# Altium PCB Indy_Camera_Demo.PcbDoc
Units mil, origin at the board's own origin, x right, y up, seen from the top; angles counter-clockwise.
Board outline 6000 x 3740.16 mil, 2 copper layers (Top Layer, Bottom Layer), stack 62.8 mil thick; 53 components, 50 nets, 311 pads, 54 vias.
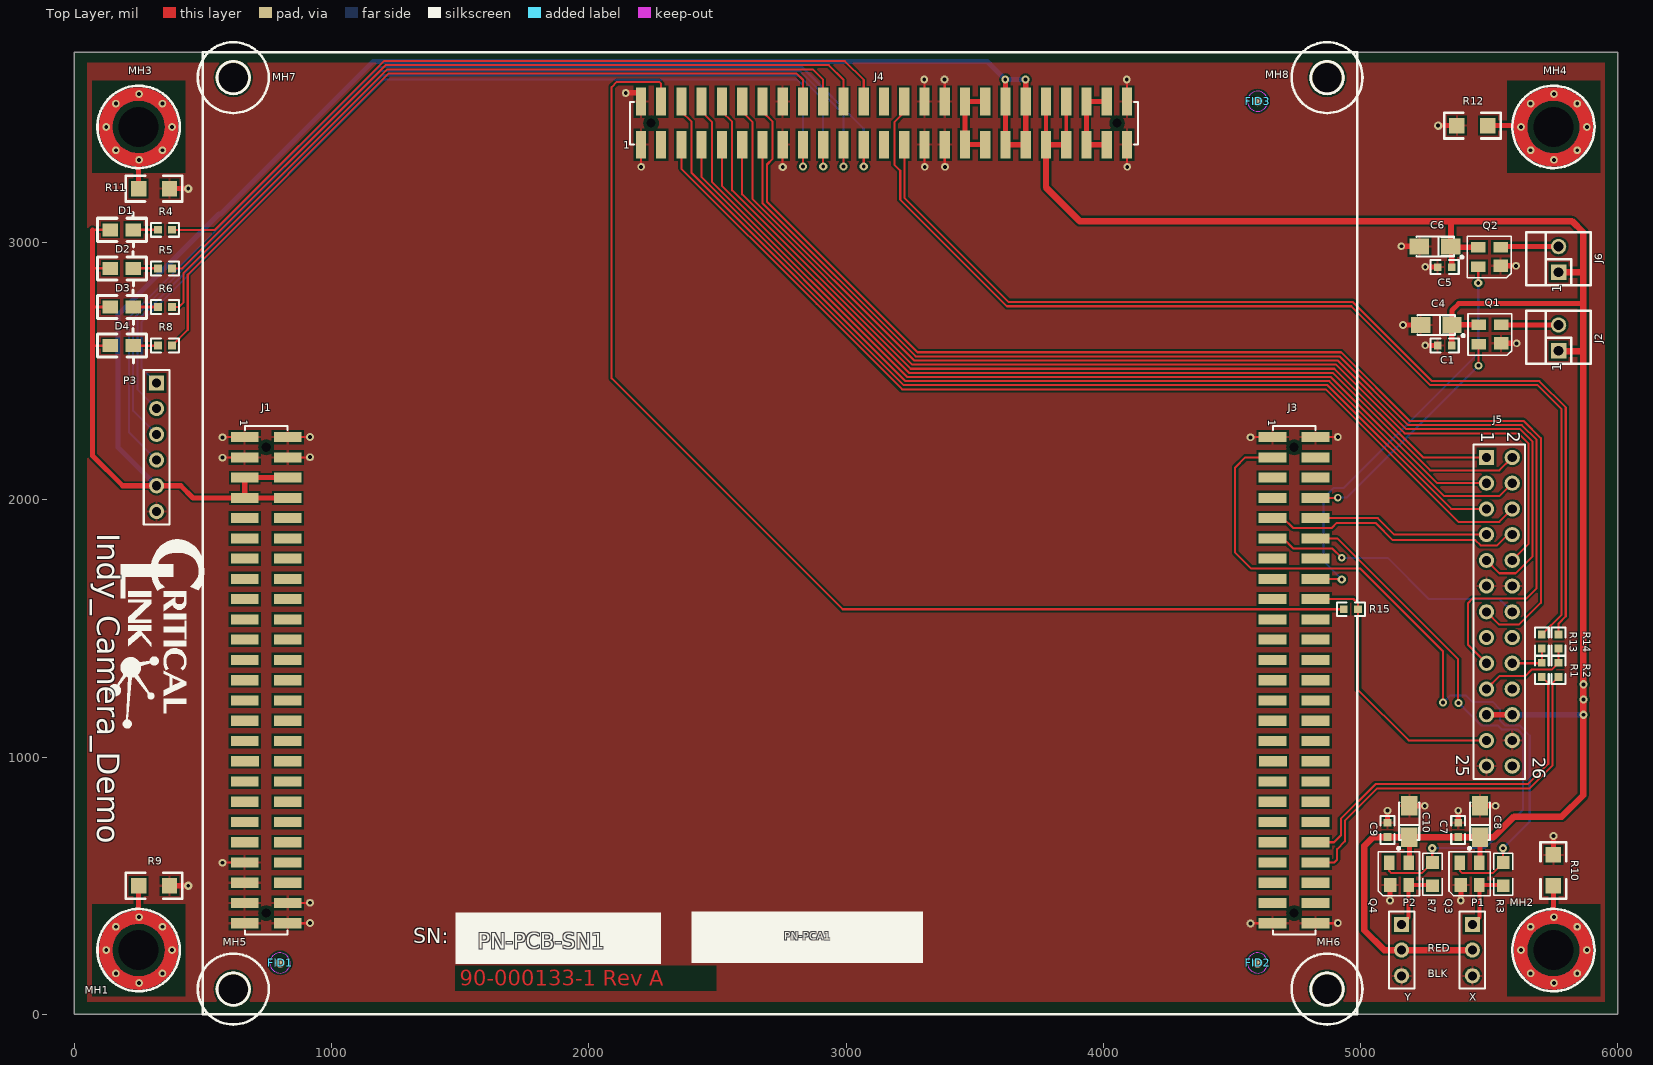
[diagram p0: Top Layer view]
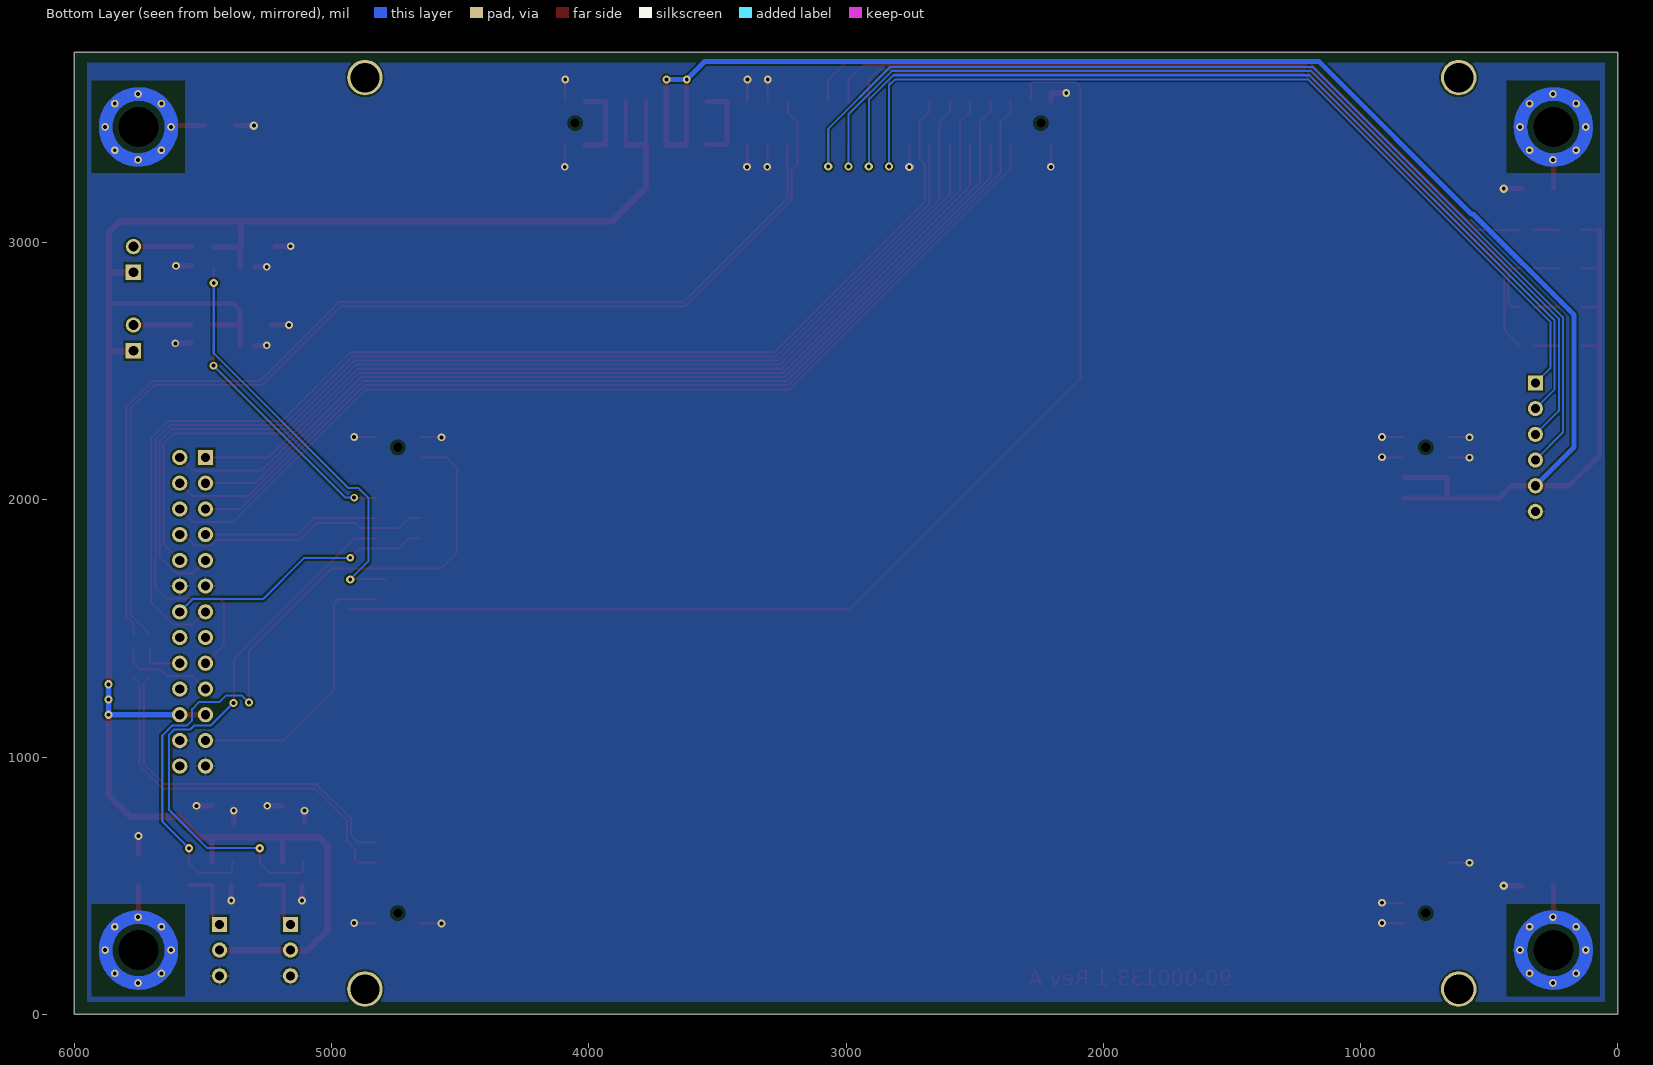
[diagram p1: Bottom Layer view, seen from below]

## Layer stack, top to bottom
Top Layer: signal copper 1.4
Dielectric: core 60, FR-4, Dk 4.8
Bottom Layer: signal copper 1.4

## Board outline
0,0 0,3740.16 6000,3740.16 6000,0

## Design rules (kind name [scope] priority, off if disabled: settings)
Clearance Clearance_pad2via [isvia vs ispad] p1: gap=16
Clearance [All] p2: gap=8
PolygonConnect PolygonConnect_via [isvia] p1: connectstyle=Direct reliefconductorwidth=10 reliefentries=4 polygonreliefangle="90 Angle"
PolygonConnect [All] p2: connectstyle=Relief reliefconductorwidth=10 reliefentries=4 polygonreliefangle="90 Angle"
RoomDefinition Indy_Camera_Demo [InComponentClass('Indy_Camera_Demo')] p1: confinementstyle=ConfineIn formatcopy=TRUE lockcomponents=FALSE outline 8500,0 9600,0 9600,2200 8500,2200
RoutingVias [All] p1: holewidth=15 width=30 viastyle="Through Hole" minholewidth=15 minwidth=28 maxholewidth=28 maxwidth=50
SilkscreenOverComponentPads [All] p1: minsilkscreentomaskgap=10
SolderMaskExpansion [All] p1: expansion=4
TestPointUsage [All] p1: valid=0 allowmultiple=FALSE
Testpoint [(IsPad And (OnTopLayer Or OnBottomLayer))] p1: side=3 testpointundercomponent=TRUE minsize=40 maxsize=100 preferedsize=60 minholesize=0 maxholesize=40 preferedholesize=32 testpointgrid=1 style=297 order=0-112345678
Width [All] p1: maxlimit=100 minlimit=8 preferedwidth=8
23 further rules are at their usual default settings.

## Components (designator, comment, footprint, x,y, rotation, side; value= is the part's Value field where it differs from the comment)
C1 "0.1uF" 0603 5355,2600 r180 top
C4 "4.7uF" SMD_TAN_A 5295,2680 r180 top
C5 "0.1uF" 0603 5355,2905 r180 top
C6 "4.7uF" SMD_TAN_A 5290,2985 r180 top
C7 "0.1uF" 0603 5380,690 r90 top
C8 "4.7uF" SMD_TAN_A 5465,750 r90 top
C9 "0.1uF" 0603 5105,690 r90 top
C10 "4.7uF" SMD_TAN_A 5190,750 r90 top
D1 "LED_0805_R" LED805 140,3050 r0 top
D2 "LED_0805_R" LED805 140,2900 r0 top
D3 "Green" LED805 140,2750 r0 top
D4 "Green" LED805 140,2600 r0 top
FID1 "FIDUCIAL" FIDUCIAL 800,200 r90 top
FID2 "FIDUCIAL" FIDUCIAL 4600,200 r90 top
FID3 "FIDUCIAL" FIDUCIAL 4600,3550 r90 top
J1 "87759-5050" 87759-5050 746.06,1299.21 r270 top locked
J2 "HDRLCK_0.1_1X2" 22-23-2021 5770,2580 r90 top
J3 "87759-5050" 87759-5050 4742.13,1299.21 r270 top locked
J4 "87759-5050" 87759-5050 3147.64,3464.57 r0 top locked
J5 "10-89-7261" HDR_M_100_2x13x240_THR_V_G 5540,1565 r270 top locked
J6 "HDRLCK_0.1_1X2" 22-23-2021 5770,2885 r90 top
MH1 "MH_5-32x" MH_5-32x#1 250,250 r0 top locked
MH2 "MH_5-32x" MH_5-32x#1 5750,250 r0 top locked
MH3 "MH_5-32x" MH_5-32x#1 250,3450 r0 top locked
MH4 "MH_5-32x" MH_5-32x#2 5750,3450 r0 top locked
MH5 "MH" MH125 618.11,98.43 r0 top locked
MH6 "MH" MH125 4870.08,98.43 r0 top locked
MH7 "MH" MH125 618.11,3641.73 r0 top locked
MH8 "MH" MH125 4870.08,3641.73 r0 top locked
P1 "22-28-4030" HDR_M_100_1x3x230_THR 5435,350 r270 top
P2 "22-28-4030" HDR_M_100_1x3x230_THR 5160,350 r270 top
P3 "22-28-4060" HDR1X6 320,2455 r270 top
PN-PCA1 "PN-PCA" PN-PCA 3300,400 r180 top
PN-PCB-SN1 "90-000133-1 Rev A" PN-PCB 1485,460 r0 top
Q1 "MIC4416YM4" SM/SOT143_1234 5547.04,2608.77 r90 top
Q2 "MIC4416YM4" SM/SOT143_1234 5545,2910 r90 top
Q3 "MIC4416YM4" SM/SOT143_1234 5390,503 r0 top
Q4 "MIC4416YM4" SM/SOT143_1234 5115.23,503.04 r0 top
R1 "0.0" 0603 5705,1367 r270 top
R2 "0.0" 0603 5770,1367 r270 top
R3 "0.0" 0805 5555,590 r270 top
R4 "1.00K" 0603 380,3050 r180 top
R5 "1.00K" 0603 380,2900 r180 top
R6 "1.00K" 0603 380,2750 r180 top
R7 "0.0" 0805 5280,590 r270 top
R8 "1.00K" 0603 380,2600 r180 top
R9 "0.0" 1206 250,500 r0 top
R10 "0.0" 1206 5750,500 r90 top
R11 "0.0" 1206 250,3210 r0 top
R12 "0.0" 1206 5495,3455 r180 top
R13 "0.0" 0603 5705,1422 r90 top
R14 "0.0" 0603 5770,1477 r270 top
R15 "0.0" 0603 4935,1575 r0 top

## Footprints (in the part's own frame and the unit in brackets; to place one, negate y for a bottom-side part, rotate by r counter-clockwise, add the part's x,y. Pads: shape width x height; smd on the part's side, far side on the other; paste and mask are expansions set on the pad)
22-23-2021 [mil] "Molex Header, Straight-Friction-Lock, 1x2"
  rect 60x60 hole 38: 1(0,0)
  round 60 hole 38: 2(100,0)
  silkscreen extent -50,-125 155,125
0603 [mil]
  rect 30x30 smd: 1(0,0) 2(55,0)
  silkscreen extent -27,-27 82,27
0805 [mil]
  rect 50x50 smd: 1(0,0) 2(90,0)
  silkscreen extent -37,-37 127,37
1206 [mil]
  rect 60x60 smd: 1(0,0) 2(120,0)
  silkscreen extent -50,-50 170,50
87759-5050 [mm] "Male Receptacle, 2x25, 2mm Pitch"
  round 0 hole 0.9 unplated: 0(-23,0) 0(23,0)
  rect 1x2.75 smd: 1(-24,-2.125) 2(-24,2.125) 3(-22,-2.125) 4(-22,2.125) 5(-20,-2.125) 6(-20,2.125) 7(-18,-2.125) 8(-18,2.125) 9(-16,-2.125) 10(-16,2.125) 11(-14,-2.125) 12(-14,2.125) 13(-12,-2.125) 14(-12,2.125) 15(-10,-2.125) 16(-10,2.125) 17(-8,-2.125) 18(-8,2.125) 19(-6,-2.125) 20(-6,2.125) 21(-4,-2.125) 22(-4,2.125) 23(-2,-2.125) 24(-2,2.125) 25(0,-2.125) 26(0,2.125) 27(2,-2.125) 28(2,2.125) 29(4,-2.125) 30(4,2.125) 31(6,-2.125) 32(6,2.125) 33(8.003,-2.1) 34(8,2.125) 35(10,-2.125) 36(10,2.125) 37(12,-2.125) 38(12,2.125) 39(14,-2.125) 40(14,2.125) 41(16,-2.125) 42(16,2.125) 43(18,-2.125) 44(18,2.125) 45(20,-2.125) 46(20,2.125) 47(22,-2.125) 48(22,2.125) 49(24,-2.125) 50(24,2.125)
  Top Layer pour cut-out: -23.762,0 -23.704,-0.292 -23.539,-0.539 -23.292,-0.704 -23,-0.762 -23,-0.762 -22.709,-0.704 -22.461,-0.539 -22.296,-0.292 -22.238,0 -22.238,0 -22.296,0.292 -22.461,0.539 -22.709,0.704 -23,0.762 -23,0.762 -23.292,0.704 -23.539,0.539 -23.704,0.292 -23.762,0
  Top Layer pour cut-out: 22.238,0 22.296,-0.292 22.461,-0.539 22.708,-0.704 23,-0.762 23,-0.762 23.291,-0.704 23.539,-0.539 23.704,-0.292 23.762,0 23.762,0 23.704,0.292 23.539,0.539 23.291,0.704 23,0.762 23,0.762 22.708,0.704 22.461,0.539 22.296,0.292 22.238,0
  Bottom Layer pour cut-out: 22.238,0 22.296,-0.292 22.461,-0.539 22.708,-0.704 23,-0.762 23,-0.762 23.291,-0.704 23.539,-0.539 23.704,-0.292 23.762,0 23.762,0 23.704,0.292 23.539,0.539 23.291,0.704 23,0.762 23,0.762 22.708,0.704 22.461,0.539 22.296,0.292 22.238,0
  Bottom Layer pour cut-out: -23.762,0 -23.704,-0.292 -23.539,-0.539 -23.292,-0.704 -23,-0.762 -23,-0.762 -22.709,-0.704 -22.461,-0.539 -22.296,-0.292 -22.238,0 -22.238,0 -22.296,0.292 -22.461,0.539 -22.709,0.704 -23,0.762 -23,0.762 -23.292,0.704 -23.539,0.539 -23.704,0.292 -23.762,0
  silkscreen extent -25.1,-2.1 25.1,2.1, body extent -24.96,-2.75 24.94,2.75, height 6.48
FIDUCIAL [mm] "Fiducial mark"
  round 1 smd paste-0.5 mask+0.5: FID(0,0)
  Top Layer keep-out circle w0.025: c0,0 r1
HDR1X6 [mm] "Connector; Header; 6 Position"
  rect 1.5x1.5 hole 0.9: 1(0,0)
  round 1.5 hole 0.9: 2(2.54,0) 3(5.08,0) 4(7.62,0) 5(10.16,0) 6(12.7,0)
  silkscreen extent -1.27,-1.27 13.97,1.27
HDR_M_100_1x3x230_THR [mm] "Connector; Header; 3 Position"
  rect 1.5x1.5 hole 0.9: 1(0,0)
  round 1.5 hole 0.9: 2(2.54,0) 3(5.08,0)
  silkscreen extent -1.27,-1.27 6.35,1.27
HDR_M_100_2x13x240_THR_V_G [mm] "Connector; Header; 13x2 Position"
  rect 1.5x1.5 hole 0.9: 1(-15.24,-1.27)
  round 1.5 hole 0.9: 2(-15.24,1.27) 3(-12.7,-1.27) 4(-12.7,1.27) 5(-10.16,-1.27) 6(-10.16,1.27) 7(-7.62,-1.27) 8(-7.62,1.27) 9(-5.08,-1.27) 10(-5.08,1.27) 11(-2.54,-1.27) 12(-2.54,1.27) 13(0,-1.27) 14(0,1.27) 15(2.54,-1.27) 16(2.54,1.27) 17(5.08,-1.27) 18(5.08,1.27) 19(7.62,-1.27) 20(7.62,1.27) 21(10.16,-1.27) 22(10.16,1.27) 23(12.7,-1.27) 24(12.7,1.27) 25(15.24,-1.27) 26(15.24,1.27)
  silkscreen extent -16.51,-2.54 16.51,2.54
LED805 [mil]
  rect 60x50 smd: 1(0,0) 2(90,0)
  silkscreen extent -50,-67 140,66
MH125 [mm] "Mounting Holes Dia 0.125,Pad 0.250"
  round 3.5 hole 2.9: 0(0,0)
  silkscreen extent -3.5,-3.5 3.5,3.5
MH_5-32x#1 [mil] "MH for screw"
  round 30 hole 15: 0(-126,0) 0(-88.51,-90.51) 0(-88.51,90.51) 0(2,-128) 0(2,128) 0(92.51,-90.51) 0(92.51,90.51) 0(130,0)
  round 0 hole 156.3 unplated mask+0: 1(0,0)
  Top Layer circle w52.5: c0,0 r128
  Bottom Layer circle w52.5: c0,0 r128
  silkscreen extent -160,-160 160,160
MH_5-32x#2 [mil] "MH for screw"
  round 30 hole 15: 0(-126,0) 0(-88.51,-90.51) 0(-88.51,90.51) 0(2,-128) 0(2,128) 0(92.51,-90.51) 0(92.51,90.51) 0(130,0)
  round 0 hole 156.3 unplated mask+0: 1(0,0)
  Top Layer circle w52.5: c0,0 r128
  Top Layer lines w52.5: -128,0 cw(c0,0) -127.98,1.98 cw(c0,0) 128,0
  Bottom Layer circle w52.5: c0,0 r128
  silkscreen extent -160,-160 160,160
PN-PCA [mil] "PN-PCA silkscreen"
  silkscreen extent 0,0 900,200
PN-PCB [mil] "PN-PCB cooper"
  silkscreen extent -4,-264 796,-64
SM/SOT143_1234 [mil]
  rect 48x56 smd: 1(0.23,0.04)
  rect 40x56 smd: 2(72.23,0.04) 3(72.23,87.04) 4(-3.77,87.04)
  silkscreen extent -46,-41 114,129
SMD_TAN_A [mm]
  rect 1.9x1.6 smd: 1(-1.55,0) 2(1.55,0)
  silkscreen extent -2.78,-1 1.85,1.17

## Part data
C1 C5 C7 C9: library part CAP_X7R_0603_50V, "CAP CER .10UF 50V X7R 10% 0603"
C4 C6 C8 C10: library part T491A475K016AT, "CAPACITOR TANT 4.7UF 16V 10% SMD"
D1 D2: "LED SUPER RED CLEAR 0805 SMD"
D3 D4: library part LED805_G, "LED THIN 565NM GRN DIFF 0805 SMD"
FID1 FID2 FID3: "Fiducial mark"
J1 J3 J4: library part HDR_M_2mm_2x25x150_SMD_V_G, "CONN HEADER 50POS 2MM VERT SMD"
J2 J6: library part 22-23-2021, "CONN HEADER 2POS .100 VERT TIN"
J5: library part HDR_M_100_2x13x240_THR_V_G, "CONN HDR DUAL 26POS .100 SRT TIN"
P1 P2: library part HDR_M_100_1x3x230_THR_V, "CONN HEADER 3POS .100 VERT TIN"
P3: library part HDR_M_100_1x6x230_THR_V, "CONN HEADER 6POS .100 VERT TIN"
PN-PCA1: "PCA Part number"
PN-PCB-SN1: library part PN-PCB-SN, "PCB Serial Number and Part Number"
Q1 Q2 Q3 Q4: "IC DRIVER MOSF LOW SIDE SOT143-4"
R1 R2 R13 R14 R15: library part ZERO_0603, "RES 0.0 OHM 1/10W 5% 0603 SMD"
R3 R7: library part ZERO_0805, "RES 0.0 OHM 1/8W 5% 0805 SMD"
R4 R5 R6 R8: library part RES_0603, "RES 1.00K OHM 1/10W 1% 0603 SMD"
R9 R10 R11 R12: library part RES_1206, "RES  0.0 OHM 1/4W 5% 1206 SMD"

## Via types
v1: diameter 30, hole 15, Top Layer to Bottom Layer, 36 vias
v2: diameter 32, hole 15, Top Layer to Bottom Layer, 18 vias

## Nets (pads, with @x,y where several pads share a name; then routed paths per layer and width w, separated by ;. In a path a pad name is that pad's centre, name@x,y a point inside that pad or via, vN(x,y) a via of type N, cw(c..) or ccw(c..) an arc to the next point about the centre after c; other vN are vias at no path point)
+3.3V: D1.1 D2.1 D3.1 D4.1 J1.5 J1.6 J1.7 J1.8 J4.37 J4.38 J4.39 J4.40 P3.5 | length 7498.9
  Top Layer w10: 72,2600 D4.1 ; 72,2750 D3.1 ; 72,3050 D1.1 ; 73,2900 D2.1
  Top Layer w20: 71,3049 71,2172 188,2055 P3.5 414,2055 461.13,2007.87 J1.7 ; J1.8 J1.7 ; J1.6 J1.5 J1.7 ; v1@3620.08,3634.44 J4.38 J4.37 J4.39 v1@3698.82,3634.44
  Bottom Layer w20: P3.5 170,2205 170,2720 562,3112 569,3112 1162,3705 3548.61,3705 v1(3619.17,3634.44) v1(3697.91,3634.44)
+5V: C1.1 C4.1 C5.1 C6.1 C7.1 C8.1 C9.1 C10.1 J2.1 J4.41 J4.42 J4.43 J4.44 J5.21 J5.22 J6.1 P1.2 P2.2 Q1.3 Q2.3 Q3.3 Q4.3 | length 8581.2
  Top Layer w15: J4.41 J4.42 ; J4.43 J4.44
  Top Layer w20: J4.41 J4.43 ; P2.2 P2.2@5161,249 ; Q4.3@5187.23,590.04 5190,592.81 C10.1 C10.1@5188.98,690 ; C6.1 C6.1@5353.8,2982.23 ; C1.1 5355,2678.98 C4.1 ; C5.1 5355,2981.02 C6.1@5353.8,2982.23 ; Q2.3 C6.1@5353.8,2982.23 ; Q1.3 5357.02,2681 C4.1 ; Q3.3 5465,592.81 C8.1 ; J5.21 J5.22 ; 5866,2763 5382,2763 5356.02,2737.02 C4.1
  Top Layer w25: J4.41 3777.56,3214.44 3908,3084 5352,3084 ; P2.2 5092,250 5015,327 5015,655 5048.98,688.98 5103.98,688.98 C9.1 5106.02,688.98 C10.1 C8.1 5516.98,688.98 5597,769 5642,769 5783,769 5866,852 5866,2578 ; P2.2@5161,250 P1.2 ; C6.1 5352,2985.98 5352,3084 ; J2.1 5772,2578 5866,2578 ; J6.1 5862,2885 5866,2889 ; 5352,3084 5822,3084 5866,3040 5866,2889 ; 5866,2578 5866,2763 5866,2889
  Bottom Layer w20: J5.22 v2(5867,1165) v2(5867,1224) v2(5867,1283)
+12VF: J4.45 J4.46 J4.47 J4.48 | length 324.8
  Top Layer w20: J4.47 J4.45 J4.46 J4.48
-12V: J4.33 J4.34 J4.35 J4.36 | length 324.2
  Top Layer w20: J4.35 3540.35,3381.89 J4.33 3462.72,3548.11 J4.34 J4.36
D0: J4.12 J5.9 | length 4490.7
  Top Layer w8: J4.12 2596.46,3509.76 2636.22,3470 2636.22,3170.41 3264.63,2542 4911.75,2542 5178.75,2275 5620.75,2275 5669,2226.75 5669,1781 5603,1715 5540,1715 J5.9
D1: J4.11 J5.10 | length 4131.8
  Top Layer w8: J4.11 2596.46,3187.54 3258,2526 4905.12,2526 5172.12,2259 5614.12,2259 5653,2220.12 5653,1828 J5.10
D1_ON_OFF: J3.8 Q1.4 | length 929.2
  Top Layer w8: J3.8 v1@4912,2007.87 ; v1(5459,2522) 5459,2604 Q1.4
  Bottom Layer w8: v1(4912,2008.78) 4945.78,2008.78 v1(5459,2522)
D2: J4.10 J5.1 | length 3723.6
  Top Layer w8: J4.10 2517.72,3509.76 2557.48,3470 2557.48,3203.89 3251.37,2510 4898.49,2510 5243.49,2165 J5.1
D2_ON_OFF: J3.16 Q2.4 | length 1655.9
  Top Layer w8: J3.16@4787.91,1692.91 J3.16 4925.09,1692.91 v2(4927,1691) ; v2(5457.96,2843) Q2.4
  Bottom Layer w8: v2(4927,1691) 4857,1761 4857,2008 4895,2046 4934,2046 5457.96,2569.96 v2(5457.96,2843)
D3: J4.9 J5.2 | length 3711
  Top Layer w8: J4.9 2517.72,3221.03 3244.75,2494 4891.86,2494 5270.86,2115 5540,2115 J5.2
D4: J4.8 J5.3 | length 3824.2
  Top Layer w8: J4.8 2438.98,3509.76 2478.74,3470 2478.74,3237.38 3238.12,2478 4885.24,2478 5298.24,2065 J5.3
D5: J4.7 J5.4 | length 3811.5
  Top Layer w8: J4.7 2438.98,3254.51 3231.49,2462 4878.61,2462 5325.61,2015 5540,2015 J5.4
D6: J4.6 J5.5 | length 3924.7
  Top Layer w8: J4.6 2360.24,3509.76 2400,3470 2400,3270.86 3224.86,2446 4871.98,2446 5352.98,1965 J5.5
D7: J4.5 J5.6 | length 3921.9
  Top Layer w8: J4.5 2360.24,3288 2885.69,2762.55 3218.24,2430 4865.35,2430 5310.39,1984.96 ; 5317.35,1978 5310.39,1984.96 ; J5.6 5540,1915 5380.35,1915 5310.39,1984.96
D8: J3.10 J5.7 | length 690.8
  Top Layer w8: J3.10 5067.87,1929.13 5132,1865 J5.7
D9: J3.9 J5.8 | length 1009.1
  Top Layer w8: J3.9 4699.87,1929.13 4738,1891 4888,1891 4908,1911 5058.3,1911 5125.3,1844 5446.47,1844 5467,1823.47 5531.53,1823.47 5573.06,1865 J5.8
EXPOSURE: J3.11 J5.14 | length 1049.7
  Top Layer w8: J3.11 4699.61,1850.39 4739,1811 4891,1811 v1(4927,1775)
  Bottom Layer w8: v1(4927,1775) 5106,1775 5266,1615 5540,1615 J5.14
FV: J4.13 J5.17 | length 4785.2
  Top Layer w8: J4.13 2675.2,3154.06 3271.26,2558 4918.37,2558 5185.37,2291 5627.37,2291 5685,2233.37 5685,1744 ; J5.17 5418,1437 5418,1599 5435,1616 5644,1616 5685,1657 5685,1744 ; 5685,1708 5685,1744
GND: C1.2 C4.2 C5.2 C6.2 C7.2 C8.2 C9.2 C10.2 J1.1 J1.2 J1.3 J1.4 J1.43 J1.45 J1.47 J1.48 J1.49 J1.50 J3.1 J3.2 J3.49 J3.50 J4.1 J4.2 J4.15 J4.16 J4.29 J4.30 J4.31 J4.32 J4.49 J4.50 J5.11 J5.12 J5.24 J5.25 P1.3 P2.3 P3.6 Q1.1 Q2.1 Q3.1 Q4.1 R9.2 R10.2 R11.2 R12.2 | length 2689.1
  Top Layer w8: v1@576.19,590.55 J1.43 ; v1@576.19,2165.35 J1.3 ; v1@576.19,2244.09 J1.1 ; J1.50 v1@915.94,354.33 ; J1.48 v1@915.94,433.07 ; J1.4 v1@915.94,2165.35 ; J1.2 v1@915.94,2244.09 ; v1@2202.76,3294.69 J4.1 ; v2(2753.94,3294.69) J4.15 ; v1@3305.12,3294.69 J4.29 ; J4.30 v1@3305.12,3634.44 ; v1@3383.86,3294.69 J4.31 ; J4.32 v1@3383.86,3634.44 ; v1@4092.52,3294.69 J4.49 ; J4.50 v1@4092.52,3634.44 ; v1@4572.25,354.33 J3.49 ; v1@4572.25,2244.09 J3.1 ; J3.50 v1@4912,354.33 ; J3.2 v1@4912,2244.09
  Top Layer w20: R9.2 v2(443,500) ; R11.2 v2(443,3210) ; v1@2146.76,3582.76 2202.76,3582.76 J4.2 ; C9.2 v1(5105,792) ; v1(5115,443) 5115.23,443.23 Q4.1@5115.23,503.04 ; v1@5159.19,2986 C6.2@5219,2986 ; v1@5174.17,2680 C4.2 ; C10.2 v1@5249.81,811.02 ; v1(5252,2601) C1.2@5299,2601 ; v1(5252,2906) 5299,2906 C5.2 ; v2(5302,3455) R12.2 ; C7.2 v1(5380,792) ; v1(5390,443) 5390.23,443.23 Q3.1 ; C8.2 v1@5524.81,811.02 ; Q2.1 v1@5604.77,2910.23 ; Q1.1 v1@5606.81,2609 ; R10.2 v2(5750,693)
  other v1: 4572.25,353.43 915.94,355.24 4912,355.24 915.94,433.98 576.19,589.65 5250.04,810.8 5525.04,810.8 576.19,2164.45 915.94,2166.26 576.19,2243.19 4572.25,2243.19 915.94,2245 4912,2245 5607.04,2608.77 5165,2680 5605,2910 5158.96,2986.23 2203.66,3294.69 3306.02,3294.69 3384.76,3294.69 4093.43,3294.69 2144,3582 3304.21,3634.44 3382.95,3634.44 4091.61,3634.44
I2C0_SCL: J5.19 R2.1 R14.2 | length 377.2
  Top Layer w8: J5.19 5540,1315 5640,1315 5665,1340 5743,1340 R2.1 R14.2
I2C0_SDA: J5.18 R1.1 R13.1 | length 213.7
  Top Layer w8: J5.18@5592,1367 J5.18 ; 5630,1365 J5.18 ; R13.1 R1.1 5703,1365 J5.18
LED_1: J4.24 R4.1 | length 3075.4
  Top Layer w8: R4.1 547.12,3050 1203.12,3706 2995.57,3706 3068.9,3632.68 J4.24
LED_2: J4.22 R5.1 | length 3048.4
  Top Layer w8: R5.1 419.75,2900 1209.75,3690 2932.83,3690 2990.16,3632.68 J4.22
  Top Layer w10: R5.1 R5.1@382,2902
LED_3: J4.20 R6.1 | length 3082.3
  Top Layer w8: R6.1 406,2750 425.07,2769.07 425.07,2882.69 1216.37,3674 2870.09,3674 2911.42,3632.68 J4.20
LED_4: J4.18 R8.1 | length 3111.8
  Top Layer w8: R8.1 441.07,2661.07 441.07,2876.07 1223,3658 2807.35,3658 2832.68,3632.68 J4.18
LV: J4.14 J5.13 | length 4710.4
  Top Layer w8: J4.14 2675.2,3509.76 2714.96,3470 2714.96,3326 2693,3304.04 2693,3158.88 3277.88,2574 4925,2574 5192,2307 5634,2307 5701,2240 5701,1600 5616,1515 5540,1515 J5.13
NetD1_2: D1.2 R4.2 | length 95
  Top Layer w10: D1.2 R4.2
NetD2_2: D2.2 R5.2 | length 95
  Top Layer w10: D2.2 R5.2
NetD3_2: D3.2 R6.2 | length 95
  Top Layer w10: D3.2 R6.2
NetD4_2: D4.2 R8.2 | length 95
  Top Layer w10: D4.2 R8.2
NetJ2_2: J2.2 Q1.2 | length 223.4
  Top Layer w20: Q1.2 5548,2680 J2.2
NetJ4_17: J4.17 P3.1 | length 3632.3
  Top Layer w8: v2(2832.68,3296.46) J4.17
  Bottom Layer w8: P3.1 261,2514 261,2691 1205,3635 2809,3635 2832.68,3611.32 v2(2832.68,3296.46)
NetJ4_19: J4.19 P3.2 | length 3817.9
  Top Layer w8: v2(2911.42,3296.46) J4.19
  Bottom Layer w8: P3.2 245,2430 245,2697.63 1198.37,3651 2815.63,3651 2911.42,3555.21 v2(2911.42,3296.46)
NetJ4_21: J4.21 P3.3 | length 4003.5
  Top Layer w8: v2(2990.16,3296.46) J4.21
  Bottom Layer w8: P3.3 229,2346 229,2704.25 1191.75,3667 2822.25,3667 2990.16,3499.1 v2(2990.16,3296.46)
NetJ4_23: J4.23 P3.4 | length 4209.2
  Top Layer w8: v2(3068.9,3296.46) J4.23
  Top Layer w10: P3.4 P3.4@340,2155
  Bottom Layer w8: P3.4 213,2262 213,2710.88 1185.12,3683 2828.88,3683 3068.9,3442.98 v2(3068.9,3296.46)
NetJ4_27: J4.27 R14.1 | length 4029.1
  Top Layer w8: J4.27 3227,3380.28 3227,3174 3632,2769 4971,2769 5278,2462 5695.63,2462 5798,2359.63 5798,1547.37 5770,1519.37 ; R14.1 5770,1519.37 ; 5770,1500 5770,1519.37
NetJ4_28: J4.28 R13.2 | length 4222.5
  Top Layer w8: J4.28 3226.38,3506.38 3188,3468 3188,3303 3211,3280 3211,3167.37 3625.37,2753 4964.37,2753 5271.37,2446 5689,2446 5782,2353 5782,1554 R13.2
NetJ6_2: J6.2 Q2.2 | length 226.2
  Top Layer w20: Q2.2 5547.73,2985 J6.2
NetMH1_0: MH1.0 R9.1 | length 122.8
  Top Layer w20: R9.1 250,380 MH1.0@252,378
NetMH2_0: MH2.0 R10.1 | length 122.8
  Top Layer w20: R10.1 5750,380 MH2.0@5752,378
NetMH3_0: MH3.0 R11.1 | length 112.8
  Top Layer w20: R11.1 250,3320 MH3.0@252,3322
NetMH4_0: MH4.0 R12.1 | length 131.1
  Top Layer w20: R12.1 5619,3455 5622.02,3451.98 MH4.0@5624,3450
PIXCLK: J3.18 J5.23 R15.2 | length 1089.2
  Top Layer w8: J3.18 4826.61,1615 4973,1615 4990,1598 R15.2 4990,1262 5187,1065 5367,1065 J5.23
PIXCLK_1: J4.4 R15.1 | length 4623.1
  Top Layer w8: J4.4 2281.5,3617.5 2274,3625 2109,3625 2089,3605 2089,2473 2987,1575 R15.1
SCLK: J3.44 R2.2 | length 1501.7
  Top Layer w8: J3.44 4897.55,590.55 4909,602 4909,642 4939.5,672.5 4939.5,753.5 5065,879 5657.63,879 5747,968.37 5747,1289 R2.2
SDAT: J3.42 R1.2 | length 1416.6
  Top Layer w8: J3.42 4897.29,669.29 4923.5,695.5 4923.5,760.13 5058.37,895 5651,895 5730,974 5730,1287 R1.2
SERVO_X: J3.3 Q3.4 R3.1 | length 2861.5
  Top Layer w8: J3.3 4552.35,2165.35 4513,2126 4513,1795 4574,1734 4998,1734 5321,1411 v2(5321,1212) ; Q3.4@5381.27,595 Q3.4 5386.23,557.77 5395,549 5514,549 R3.1 ; R3.1@5554,591 v2(5554,646)
  Bottom Layer w8: v2(5321,1212) 5348,1239 5411,1239 5435,1215 5514,1215 5542,1187 5542,1143 5561.53,1123.47 5618.21,1123.47 5658,1083.68 5658,750 v2(5554,646)
SERVO_Y: J3.12 Q4.4 R7.1 | length 2209.9
  Top Layer w8: J3.12 4909.61,1850.39 5380,1380 v2@5380,1213 ; Q4.4@5106.27,595 5111.23,590.04 5111.23,557.77 5120,549 5239,549 R7.1 5279,591 v2(5279,646)
  Bottom Layer w8: v2(5279,646) 5483,646 5631.53,794.53 5631.53,1087.53 5611.58,1107.47 5548.53,1107.47 5532.53,1123.47 5468.53,1123.47 v2(5381,1211)
X: P1.1 Q3.2 R3.2 | length 258.3
  Top Layer w15: P1.1 5462.23,377.23 Q3.2 5551.96,503.04 R3.2
Y: P2.1 Q4.2 R7.2 | length 262.6
  Top Layer w15: P2.1 5187.23,377.23 5187.23,503.04 R7.2@5276.96,503.04 ; R7.2@5276.96,503.04 R7.2 R7.2@5276.96,503.04
pads on no net: FID1.FID FID2.FID FID3.FID J1.0 J1.9 J1.10 J1.11 J1.12 J1.13 J1.14 J1.15 J1.16 J1.17 J1.18 J1.19 J1.20 J1.21 J1.22 J1.23 J1.24 J1.25 J1.26 J1.27 J1.28 J1.29 J1.30 J1.31 J1.32 J1.33 J1.34 J1.35 J1.36 J1.37 J1.38 J1.39 J1.40 J1.41 J1.42 J1.44 J1.46 J3.0 J3.4 J3.5 J3.6 J3.7 J3.13 J3.14 J3.15 J3.17 J3.19 J3.20 J3.21 J3.22 J3.23 J3.24 J3.25 J3.26 J3.27 J3.28 J3.29 J3.30 J3.31 J3.32 J3.33 J3.34 J3.35 J3.36 J3.37 J3.38 J3.39 J3.40 J3.41 J3.43 J3.45 J3.46 J3.47 J3.48 J4.0 J4.3 J4.25 J4.26 J5.15 J5.16 J5.20 J5.26 MH1.1 MH2.1 MH3.1 MH4.1 MH5.0 MH6.0 MH7.0 MH8.0

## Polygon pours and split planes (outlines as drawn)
GND on Top Layer "Top_GND" (solid, pour order 1000): 50,50 50,3700 5950,3700 5950,50 5750,50
GND on Bottom Layer "Bot_GND" (solid, pour order 1001): 50,50 50,3700 5950,3700 5950,50 5750,50

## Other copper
Top Layer:
  pour cut-out: 70,429 432,429 432,71 70,71
  pour cut-out: 5570,429 5932,429 5932,71 5570,71
  pour cut-out: 5570,3629 5932,3629 5932,3271 5570,3271
  pour cut-out: 70,3629 432,3629 432,3271 70,3271
Bottom Layer:
  pour cut-out: 70,429 432,429 432,71 70,71
  pour cut-out: 5570,429 5932,429 5932,71 5570,71
  pour cut-out: 5570,3629 5932,3629 5932,3271 5570,3271
  pour cut-out: 70,3629 432,3629 432,3271 70,3271

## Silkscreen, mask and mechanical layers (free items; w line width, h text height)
Top Overlay:
  drawing of 29 lines, arcs and shapes, not listed
  text "Indy_Camera_Demo" at 60,1870 h150 r270
  text "RED" at 5262,234 h50
  text "BLK" at 5262,134 h50
  text "Y" at 5172,43 h50
  text "X" at 5422,43 h50
Outline:
  the board outline again, w10
Stackup:
  lines w10: 9480,1798.33 12500,1798.33 ; 9480,1972.33 12500,1972.33 ; 9420,536 ccw(c9476,536) 9476,480 12504,480 ccw(c12504,536) 12560,536 12560,2394 ccw(c12504,2394) 12504,2450 9476,2450 ccw(c9476,2394) 9420,2394 9420,536
  text "Layer Stack Up Detail for: Indy_Camera_Demo.PcbDoc" at 9480,2168.97 h59
  text "Layer" at 9480,1907.33 h40
  text "Gerber" at 10543.69,1907.33 h40
  text "Dielectric" at 11065.83,1907.33 h40
  text "Dielectric" at 11849.61,1907.33 h40
  text "Name" at 9480,1827.33 h40
  text "Document" at 10543.69,1827.33 h40
  text "Material" at 11065.83,1827.33 h40
  text "Type" at 11849.61,1827.33 h40
  text "Top Solder Mask" at 9480,1654.17 h56
  text "(.GTS)" at 10543.69,1654.17 h56
  text "Solder Resist" at 11065.83,1654.17 h56
  text "Top Layer" at 9480,1375.83 h56
  text "(.GTL)" at 10543.69,1375.83 h56
  text "FR4" at 11065.83,1236.67 h56
  text "Core" at 11849.61,1236.67 h56
  text "Bottom Layer" at 9480,1097.5 h56
  text "(.GBL)" at 10543.69,1097.5 h56
  text "Bottom Solder Mask" at 9480,819.17 h56
  text "(.GBS)" at 10543.69,819.17 h56
  text "Solder Resist" at 11065.83,819.17 h56
Notes:
  text "Fabrication Notes:" at -1024,-1386 h200
  text "1. Fabricate printed circuit board per IPC 6012 Class 2." at -1024,-1586 h150
  text "2. Board material: FR4 laminate, .062\" nominal finished thickness." at -1024,-1786 h150
  text "3. Copper plating: 1.0oz on outer layers and 0.001\" min in PTH." at -1024,-1986 h150
  text "4. HASL finish." at -1024,-2186 h150
  text "5. Solder mask: LPI, 1-side, green.  Silkscreen: 1-side, white." at -1024,-2386 h150
  text "6. All boards shall be 100% electrical tested by fabricator netlist." at -1024,-2586 h150
Template:
  drawing of 2067 lines, arcs and shapes, not listed
  text "1" at -98.66,7865 h70
  text "2" at 2727,7865 h70
  text "3" at 5552,7865 h70
  text "4" at 8393.01,7865 h70
  text "5" at 11227,7865 h70
  text "6" at 14062,7865 h70
  text "PROPRIETARY" at -709.5,7700.5 h100
  text "REV" at 12822,7672 h80
  text "DESCRIPTION" at 13089,7669 h80
  text "DATE" at 15034.5,7666 h80
  text "INITIALS" at 14624,7663 h80
  text "THIS DOCUMENT CONTAINS PROPRIETARY INFORMATION. ANY" at -1289.5,7630.5 h60
  text "REPRODUCTION, DISCLOSURE, OR USE OF THIS DOCUMENT IS" at -1289.5,7570.5 h60
  text "EXPRESSLY PROHIBITED EXCEPT BY WRITTEN AGREEMENT" at -1289.5,7510.5 h60
  text "A" at 12870,7480 h80
  text "Initial release." at 13080,7480 h80
  text "O.V" at 14720,7480 h80
  text "11-30-10" at 14980,7480 h80
  text "WITH" at -1289.5,7460.5 h60
  text "WITH" at -1289.5,7460.5 h60
  text "WITH" at -1289.5,7460.5 h60
  text "WITH" at -1289.5,7460.5 h60
  text "WITH" at -1289.5,7460.5 h60
  text "WITH" at -1289.5,7460.5 h60
  text "CRITICAL LINK, LLC." at -1131,7460.5 h60
  text "General Notes:" at -1100,7200 h200
  text "All dimensions are in mils (0.001\") unless otherwise specified." at -1100,7000 h150
  text "Tolerance on all dimensions shall be ±.005\" unless otherwise specified." at -1100,6800 h150
  text "A" at -1425,6622 h70
  text "A" at 15375,6622 h70
  text "B" at -1425,3888.02 h70
  text "B" at 15375,3888.02 h70
  text "C" at -1425,1107 h70
  text "C" at 15375,1107 h70
  text "ENGINEER:" at 9310,-1695 h45
  text "TITLE:" at 10860,-1700 h45
  text "D" at -1425,-1715 h70
  text "D" at 15375,-1715 h70
  text "David Rice" at 9480,-1800 h100
  text "Indy Camera Demo" at 10990,-1970 h210
  text "PCB DESIGNER:" at 9310,-1990 h45
  text "Oscar Valera" at 9470,-2115 h100
  text "DATE:" at 9320,-2300 h45
  text "PART NO.:" at 10860,-2300 h45
  text "REV:" at 12970,-2310 h45
  text "SIZE:" at 13390,-2310 h45
  text "Critical Link, LLC" at 14025,-2360 h70
  text "90-000133-1" at 11115,-2395 h100
  text ".PRINT_DATE" at 9370,-2420 h70
  text "A" at 13140,-2440 h200
  text "B" at 13560,-2440 h200
  text "6712 Brooklawn Pkwy" at 14020,-2470 h70
  text "Syracuse, NY 13211" at 14020,-2575 h70
  text "FILE NAME:" at 9320,-2600 h45
  text "PRINT NAME:" at 10860,-2600 h45
  text "SCALE:" at 12960,-2600 h45
  text "315.425.4045" at 14020,-2680 h60
  text ".Print_Scale" at 13120,-2685 h90
  text ".Printout_Name" at 11120,-2700 h100
  text ".PCB_FILE_NAME_NO_PATH" at 9370,-2720 h70
  text "www.criticallink.com" at 14010,-2770 h70
  text "1" at -98.66,-2935 h70
  text "2" at 2727,-2935 h70
  text "3" at 5552,-2935 h70
  text "4" at 8393.01,-2935 h70
  text "5" at 11227,-2935 h70
  text "6" at 14062,-2935 h70
Drill Drawing:
  text ".LEGEND" at 9500,2800 h50

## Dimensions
0,3740.16 to 250,3450 on Dimensions
0,0 to 618.11,98.43 on Dimensions
250,3450 to 5750,3450 on Dimensions
5750,250 to 5750,3450 on Dimensions
6000,0 to 5750,250 on Dimensions
0,0 to 618.11,98.43 on Dimensions
250,250 to 5750,250 on Dimensions
250,250 to 250,3450 on Dimensions
0,0 to 250,250 on Dimensions
0,0 to 250,250 on Dimensions
0,0 to 6000,0 on Dimensions
0,0 to 0,3740.16 on Dimensions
